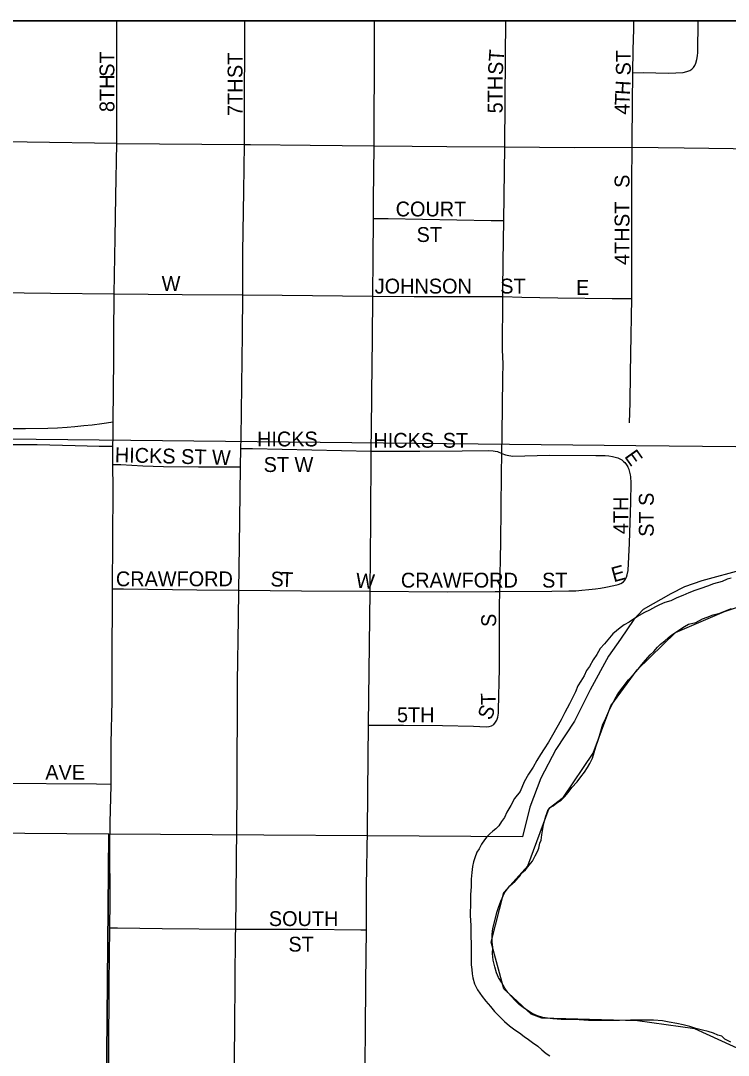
# Model space of a CAD drawing. Extents: x -17 to 88, y -5 to 22.
# Drawn here: x 3.658 to 4.109, y 20.24 to 20.9 of the extents above; entities that cross this region are included whole.
import ezdxf

# ---------------------------------------------------------------- set-up
doc = ezdxf.new("R2010")
doc.units = 0
for name, color, linetype in [('GM_X_City_Street', 7, 'Continuous'), ('GM_X_City_Street_Text', 7, 'Continuous'), ('GM_X_Corporation', 7, 'Continuous'), ('GM_X_Major_River', 7, 'Continuous'), ('GM_X_Rail_Line', 7, 'Continuous'), ('GM_X_Section', 7, 'Continuous'), ('GM_X_State_Route', 7, 'Continuous'), ('GM_X_Township', 7, 'Continuous'), ('SH_Data', 7, 'Continuous')]:
    doc.layers.add(name, color=color, linetype=linetype)

msp = doc.modelspace()

# ---------------------------------------------------------------- linework, layer by layer
at = {"layer": 'GM_X_City_Street'}
for points in [[(3.71903, 20.82161), (3.71905, 20.87247), (3.71906, 20.9)], [(3.8005, 20.82106), (3.80056, 20.85191), (3.80063, 20.88234), (3.80074, 20.9)], [(3.96636, 20.81956), (3.96675, 20.87713), (3.96712, 20.9)], [(4.04809, 20.86685), (4.04824, 20.88132), (4.04856, 20.89464), (4.04871, 20.9)], [(4.04809, 20.86685), (4.05469, 20.86693), (4.07085, 20.86659), (4.08019, 20.86695), (4.0824, 20.8675), (4.08431, 20.86828), (4.08553, 20.8691), (4.08673, 20.87018), (4.08747, 20.87139), (4.08819, 20.8729), (4.08885, 20.8752), (4.08927, 20.87749), (4.08946, 20.87962), (4.08967, 20.9)], [(4.04763, 20.81925), (4.0476, 20.82211), (4.04787, 20.84741), (4.04809, 20.86685)], [(3.79937, 20.72521), (3.79949, 20.75244), (3.80006, 20.79126), (3.8005, 20.82106)], [(3.88311, 20.8202), (3.9073, 20.81991), (3.92938, 20.81978), (3.96636, 20.81956)], [(3.96569, 20.77249), (3.96636, 20.81956)], [(3.96636, 20.81956), (4.01051, 20.81915), (4.04763, 20.81925)], [(4.04732, 20.72289), (4.04743, 20.73021), (4.04732, 20.77351), (4.04748, 20.79726), (4.04763, 20.81925)], [(4.04763, 20.81925), (4.08069, 20.81887)], [(4.08069, 20.81887), (4.12779, 20.81833)], [(3.8827, 20.77393), (3.89199, 20.77377), (3.95778, 20.77263), (3.96569, 20.77249)], [(3.96506, 20.7241), (3.96508, 20.72788), (3.96532, 20.74651), (3.96569, 20.77249)], [(3.62637, 20.72681), (3.67687, 20.72619), (3.71749, 20.72582)], [(3.71749, 20.72582), (3.76073, 20.72543), (3.79937, 20.72521)], [(3.79816, 20.6273), (3.79826, 20.63406), (3.79926, 20.70024), (3.79937, 20.72521)], [(3.79937, 20.72521), (3.82445, 20.72506), (3.88224, 20.72429)], [(3.88224, 20.72429), (3.90857, 20.7241), (3.93743, 20.7241), (3.95898, 20.7241), (3.96506, 20.7241)], [(3.96458, 20.6241), (3.96474, 20.63637), (3.96522, 20.67226), (3.96534, 20.68114), (3.96497, 20.69014), (3.96506, 20.7241)], [(3.96506, 20.7241), (3.97723, 20.7237), (4.00017, 20.72329), (4.03487, 20.72296), (4.04581, 20.72289), (4.04732, 20.72289)], [(4.04594, 20.64348), (4.04622, 20.65649), (4.04652, 20.67509), (4.04678, 20.68756), (4.04732, 20.72289)], [(3.62542, 20.6402), (3.6409, 20.64002), (3.66078, 20.63987), (3.67505, 20.64021), (3.68133, 20.64041), (3.68742, 20.64081), (3.6923, 20.64116), (3.69797, 20.6418), (3.70327, 20.64231), (3.70958, 20.64307), (3.71672, 20.64412)], [(3.62134, 20.62971), (3.6434, 20.62981), (3.65022, 20.62978), (3.66829, 20.62974), (3.69256, 20.62913), (3.70785, 20.62879), (3.7166, 20.62863)], [(3.79798, 20.61548), (3.79816, 20.6273)], [(3.79816, 20.6273), (3.80563, 20.62714), (3.88127, 20.62552)], [(3.88127, 20.62552), (3.9123, 20.62561), (3.93912, 20.62579), (3.95578, 20.6259), (3.95891, 20.62578), (3.96027, 20.62553), (3.96167, 20.6252), (3.96458, 20.6241)], [(3.96323, 20.53602), (3.96377, 20.56742), (3.96437, 20.61084), (3.96458, 20.6241)], [(3.96458, 20.6241), (3.9668, 20.62323), (3.96791, 20.6229), (3.96907, 20.62265), (3.97145, 20.62241), (3.99464, 20.62303), (4.0245, 20.62285), (4.02746, 20.62275), (4.03037, 20.62264), (4.03276, 20.62243), (4.03502, 20.62209), (4.03683, 20.62169), (4.03835, 20.62124), (4.03967, 20.62058), (4.0409, 20.61988), (4.04213, 20.61898), (4.04287, 20.61824), (4.04398, 20.61688), (4.04489, 20.61548)], [(3.71661, 20.61711), (3.72166, 20.61694), (3.73565, 20.61617), (3.74882, 20.61565), (3.77123, 20.61546), (3.79386, 20.61548), (3.79798, 20.61548)], [(3.79687, 20.53693), (3.79727, 20.56515), (3.79798, 20.61548)], [(4.04203, 20.54216), (4.04322, 20.5435), (4.04407, 20.54518), (4.04447, 20.54665), (4.04495, 20.54945), (4.0458, 20.56683), (4.04674, 20.59297), (4.04687, 20.6054), (4.04665, 20.60914), (4.04649, 20.61047), (4.04611, 20.61218), (4.04564, 20.61385), (4.04489, 20.61548)], [(3.7164, 20.53771), (3.72341, 20.53762), (3.77015, 20.53718), (3.79687, 20.53693)], [(3.96323, 20.53602), (3.99638, 20.53617), (4.00724, 20.5364), (4.01164, 20.53652), (4.01558, 20.53678), (4.01989, 20.53724), (4.02431, 20.53779), (4.02744, 20.53823), (4.03078, 20.53875), (4.03591, 20.53976), (4.03858, 20.54053), (4.04043, 20.5412), (4.04203, 20.54216)], [(3.79486, 20.32081), (3.7953, 20.36379), (3.79574, 20.40768), (3.79606, 20.47847), (3.79661, 20.51882), (3.79687, 20.53693)], [(3.79687, 20.53693), (3.83688, 20.53653), (3.88058, 20.53627)], [(3.87955, 20.45087), (3.88368, 20.45085), (3.9018, 20.45075), (3.92661, 20.4506), (3.94642, 20.45021), (3.95448, 20.4498), (3.95646, 20.44996), (3.95794, 20.45029), (3.95934, 20.4512), (3.96057, 20.4526), (3.96132, 20.45408), (3.96196, 20.45597), (3.96229, 20.45852), (3.96245, 20.46048), (3.96293, 20.48688), (3.96306, 20.52666), (3.96323, 20.53602)], [(3.88058, 20.53627), (3.92963, 20.53589), (3.96032, 20.53601), (3.96323, 20.53602)], [(3.52389, 20.41445), (3.56376, 20.41436), (3.64204, 20.41384), (3.70612, 20.4133), (3.71541, 20.41323)], [(3.71464, 20.32153), (3.71951, 20.32147), (3.74808, 20.32112), (3.79486, 20.32081)], [(3.79373, 20.17177), (3.79399, 20.21926), (3.79429, 20.25885), (3.79482, 20.31659), (3.79486, 20.32081)], [(3.79486, 20.32081), (3.80776, 20.32072), (3.8409, 20.32067), (3.87467, 20.32037), (3.87815, 20.32034)]]:
    msp.add_lwpolyline(points, dxfattribs=at)
at = {"layer": 'GM_X_Corporation'}
msp.add_line((5.58768, 20.9), (3.20786, 20.9), dxfattribs=at)
msp.add_lwpolyline([(4.11966, 20.24242), (4.08749, 20.25708), (4.05108, 20.26229), (3.98996, 20.26389), (3.98314, 20.2666), (3.9658, 20.28267), (3.95766, 20.31233), (3.96586, 20.34414), (3.98117, 20.3611), (3.99473, 20.3978), (4.00389, 20.40494), (4.0227, 20.43287), (4.03393, 20.46314), (4.05081, 20.48616), (4.07528, 20.50988), (4.10651, 20.5233), (4.1518, 20.53813)], dxfattribs=at)
at = {"layer": 'GM_X_Major_River'}
for points in [[(4.11074, 20.54453), (4.10808, 20.54379), (4.10503, 20.5423), (4.09933, 20.54082), (4.09552, 20.53933), (4.09133, 20.53785), (4.08753, 20.53674), (4.08372, 20.53525), (4.07991, 20.53338), (4.0761, 20.53189), (4.07229, 20.53002), (4.06849, 20.52892), (4.06506, 20.52742), (4.06239, 20.52631), (4.05858, 20.52406), (4.05553, 20.52256), (4.0521, 20.52069), (4.04905, 20.51882), (4.04561, 20.51657), (4.04256, 20.51469), (4.03989, 20.51282), (4.0376, 20.51094), (4.03531, 20.50906), (4.02994, 20.50265), (4.02726, 20.49963), (4.02496, 20.49586), (4.02266, 20.49246), (4.02035, 20.4883), (4.01843, 20.48566), (4.01689, 20.48226), (4.01496, 20.47886), (4.01304, 20.47584), (4.0115, 20.47206), (4.00957, 20.46827), (4.00764, 20.46449), (4.00457, 20.45883), (4.00225, 20.45429), (3.99956, 20.44938), (3.99687, 20.44447), (3.99418, 20.43993), (3.99149, 20.43578)], [(3.99539, 20.39819), (3.9973, 20.39931), (3.99959, 20.40119), (4.00226, 20.40307), (4.00456, 20.40533), (4.00685, 20.40796), (4.00915, 20.41098), (4.0126, 20.41475), (4.0149, 20.41777), (4.0172, 20.42079), (4.01912, 20.42381), (4.02066, 20.42645), (4.0222, 20.42985), (4.02336, 20.43326), (4.02453, 20.43705), (4.02609, 20.44197), (4.02764, 20.44689), (4.02881, 20.45143), (4.03074, 20.45521), (4.03267, 20.45975), (4.0346, 20.46353), (4.03652, 20.46731), (4.03845, 20.47071), (4.04535, 20.47977), (4.04841, 20.48316), (4.05147, 20.48655), (4.05377, 20.48956), (4.05607, 20.4922), (4.05913, 20.49559), (4.06142, 20.49785), (4.06372, 20.50049), (4.06564, 20.50238), (4.06831, 20.50463), (4.0706, 20.50651), (4.07289, 20.50839), (4.07594, 20.51027), (4.07861, 20.51214), (4.0809, 20.51364), (4.08357, 20.51514), (4.08814, 20.51624), (4.09233, 20.51849), (4.09538, 20.5196), (4.09918, 20.52109), (4.10337, 20.5222), (4.10718, 20.52369), (4.11098, 20.52518)], [(3.99149, 20.43578), (3.98918, 20.432), (3.98688, 20.42823), (3.98457, 20.42407), (3.9815, 20.41954), (3.9788, 20.41463), (3.9761, 20.40858), (3.97265, 20.40405), (3.97034, 20.39952), (3.96765, 20.39536), (3.96611, 20.39196), (3.96419, 20.38932), (3.96265, 20.38667), (3.96074, 20.38479), (3.95883, 20.38329), (3.95692, 20.38141), (3.95501, 20.37952), (3.95348, 20.37764), (3.95156, 20.375), (3.95002, 20.37197), (3.94848, 20.36971), (3.94732, 20.3663), (3.94654, 20.36365), (3.94576, 20.36062), (3.94535, 20.35683), (3.94494, 20.35266), (3.94491, 20.34773), (3.94449, 20.3428), (3.94446, 20.33787), (3.94439, 20.32952), (3.94473, 20.32307), (3.94468, 20.317), (3.94501, 20.31054), (3.94492, 20.29802), (3.94528, 20.29499), (3.94564, 20.29232), (3.946, 20.28967), (3.94711, 20.28586), (3.94898, 20.28205), (3.95199, 20.27786), (3.95425, 20.27481), (3.95726, 20.27137), (3.9599, 20.26831), (3.96291, 20.26525), (3.9663, 20.26181), (3.96932, 20.25913), (3.97272, 20.25645), (3.97574, 20.25453), (3.97876, 20.25223), (3.98141, 20.25031), (3.98405, 20.2484), (3.98745, 20.24609), (3.9901, 20.2438), (3.99274, 20.2415), (3.995, 20.23997)], [(4.11049, 20.24857), (4.10671, 20.2505), (4.10483, 20.25241), (4.10217, 20.25319), (4.09953, 20.25434), (4.09612, 20.25551), (4.09232, 20.2563), (4.08816, 20.25747), (4.08437, 20.25864), (4.0802, 20.25981), (4.07603, 20.2606), (4.0711, 20.26139), (4.06693, 20.26218), (4.06124, 20.2626), (4.0563, 20.26264), (4.05174, 20.26268), (4.04643, 20.26272), (4.03959, 20.26239), (4.03276, 20.26244), (4.0263, 20.26249), (4.01985, 20.26254), (4.01378, 20.26297), (4.0077, 20.26302), (4.00239, 20.26306), (3.99707, 20.26347), (3.99366, 20.26388), (3.99062, 20.26428), (3.98721, 20.26545), (3.98381, 20.26699), (3.98078, 20.26891), (3.97814, 20.27083), (3.97549, 20.27275), (3.97286, 20.27542), (3.9706, 20.27772), (3.96834, 20.28039), (3.96646, 20.28306), (3.96421, 20.28687), (3.96233, 20.28992), (3.96121, 20.29296), (3.9601, 20.29677), (3.95899, 20.30095), (3.95864, 20.30513), (3.95867, 20.30892), (3.95832, 20.31272), (3.95835, 20.31727), (3.95876, 20.32106), (3.9615, 20.33205), (3.96266, 20.33507), (3.96382, 20.33848), (3.96537, 20.34188), (3.96653, 20.34453), (3.96806, 20.34641), (3.96959, 20.3483), (3.97303, 20.35131), (3.97571, 20.35432), (3.97724, 20.35659), (3.97953, 20.35847), (3.98184, 20.36149), (3.98413, 20.36412), (3.98568, 20.36753), (3.98721, 20.37017), (3.98799, 20.37244), (3.98877, 20.37547), (3.98954, 20.37736), (3.98995, 20.38077), (3.99035, 20.38343), (3.99075, 20.38608), (3.99153, 20.38873), (3.99231, 20.39214), (3.99309, 20.39441), (3.99386, 20.3963), (3.99539, 20.39819)]]:
    msp.add_lwpolyline(points, dxfattribs=at)
at = {"layer": 'GM_X_Rail_Line'}
msp.add_lwpolyline([(3.33784, 20.63494), (3.42428, 20.63515), (3.66767, 20.63326), (4.04986, 20.62913), (4.41143, 20.62553), (4.69708, 20.62244), (4.78173, 20.62035), (4.83124, 20.61775), (4.87795, 20.61471), (5.02378, 20.6032), (5.35564, 20.57743), (5.53204, 20.56318), (5.63047, 20.55545), (5.71669, 20.54875), (6.32595, 20.50065), (6.53551, 20.48433), (6.65266, 20.47472), (6.95205, 20.45153), (7.27068, 20.42662), (7.45962, 20.41202), (8.17109, 20.35637), (8.73122, 20.31274), (9.05827, 20.28714), (9.4, 20.26034)], dxfattribs=at)
at = {"layer": 'GM_X_Section'}
for points in [[(2.68666, 20.9), (2.68345, 20.1757), (3.71204, 20.17028), (3.71394, 20.3813), (3.41881, 20.38356), (3.42344, 20.9)], [(4.11857, 20.55006), (4.09199, 20.54273), (4.08097, 20.53903), (4.07221, 20.53457), (4.05469, 20.52449), (4.04857, 20.51811), (4.04012, 20.50568), (4.03245, 20.49476), (4.02089, 20.47327), (4.01086, 20.45328), (3.99896, 20.43519), (3.98932, 20.4171), (3.98233, 20.39859), (3.97762, 20.37969), (3.71394, 20.3813), (3.71204, 20.17028), (3.7219, 20.17019), (4.7146, 20.17531)]]:
    msp.add_lwpolyline(points, dxfattribs=at)
at = {"layer": 'GM_X_State_Route'}
for points in [[(3.88311, 20.8202), (3.88326, 20.8859), (3.88344, 20.9)], [(3.71903, 20.82161), (3.66193, 20.82246), (3.60534, 20.82288), (3.55935, 20.82357), (3.52839, 20.82388), (3.48662, 20.82431), (3.44748, 20.82449), (3.4259, 20.82461)], [(3.71665, 20.63482), (3.71672, 20.64412), (3.71718, 20.68438), (3.71722, 20.69932), (3.71749, 20.72582), (3.71806, 20.76161), (3.71849, 20.78812), (3.71903, 20.82161)], [(3.71903, 20.82161), (3.8005, 20.82106), (3.80437, 20.82104), (3.84237, 20.8206), (3.88311, 20.8202)], [(3.88139, 20.63749), (3.88163, 20.66267), (3.88197, 20.6974), (3.88224, 20.72429), (3.88247, 20.74907), (3.8827, 20.77393), (3.8828, 20.78567), (3.88311, 20.8202)], [(3.87827, 20.34126), (3.87829, 20.34821), (3.87883, 20.38351), (3.87933, 20.43065), (3.87955, 20.45087), (3.87955, 20.45104), (3.88058, 20.53627), (3.88093, 20.58133), (3.88127, 20.62552), (3.8813, 20.62915), (3.88139, 20.63749)], [(3.71363, 20.21548), (3.71396, 20.241), (3.7142, 20.28577), (3.71464, 20.32153), (3.71484, 20.3384), (3.71465, 20.37439), (3.71492, 20.38863), (3.71541, 20.41231), (3.71541, 20.41323), (3.71548, 20.43901), (3.71606, 20.46624), (3.71622, 20.4978), (3.71627, 20.5282), (3.7164, 20.53771), (3.71657, 20.56923), (3.71675, 20.60152), (3.71661, 20.61711), (3.7166, 20.62863), (3.71665, 20.63482)], [(3.87902, 20.10973), (3.87948, 20.13681), (3.8796, 20.15415), (3.8795, 20.17145), (3.87945, 20.18219), (3.87932, 20.1885), (3.87908, 20.19275), (3.87779, 20.22658), (3.87741, 20.23657), (3.87756, 20.25519), (3.8778, 20.28698), (3.87815, 20.32034), (3.87822, 20.32775), (3.87827, 20.34126)]]:
    msp.add_lwpolyline(points, dxfattribs=at)
at = {"layer": 'GM_X_Township'}
msp.add_line((7.72185, 20.9), (2.68822, 20.9), dxfattribs=at)
at = {"layer": 'SH_Data'}
msp.add_line((2.6, 20.9), (9.4, 20.9), dxfattribs=at)

# ---------------------------------------------------------------- texts
at = {"layer": 'GM_X_City_Street_Text'}
for s, rotation, p in [('ST', 86.42535, (3.96505, 20.86519)), ('ST', 90, (4.04671, 20.86508)), ('ST', 90, (3.71754, 20.86424)), ('ST', 90, (3.79921, 20.86341)), ('8TH', 90, (3.71754, 20.84174)), ('7TH', 90, (3.79921, 20.83924)), ('5TH', 90, (3.96504, 20.84091)), ('H', 86.69771, (4.04617, 20.85243)), ('T', 87.97798, (4.04593, 20.84582)), ('4', 89.40676, (4.04587, 20.84005)), ('S', 90, (4.04587, 20.79341)), ('COURT', 0.00001, (3.89682, 20.77519)), ('ST', 90, (4.04587, 20.76841)), ('ST', 0.00001, (3.91016, 20.7589)), ('4TH', 90, (4.04587, 20.74424)), ('W', 0.00001, (3.74766, 20.72769)), ('JOHNSON', 0.00001, (3.88349, 20.72603)), ('ST', 0.00001, (3.96349, 20.72603)), ('E', 0.00001, (4.01182, 20.72519)), ('HICKS', 0.00001, (3.80849, 20.62853)), ('HICKS', 0.00001, (3.88266, 20.62769)), ('ST', 0.00001, (3.92682, 20.62769)), ('HICKS ST W', 358.53177, (3.71773, 20.61852)), ('E', 305.2252, (4.04229, 20.62214)), ('ST W', 0.00001, (3.81266, 20.61223)), ('ST S', 90, (4.06133, 20.57091)), ('4TH', 90, (4.04504, 20.57257)), ('E', 15.2454, (4.03581, 20.54186)), ('CRAWFORD', 0.00001, (3.71849, 20.53936)), ('S', 357.64932, (3.8169, 20.53936)), ('T', 357.64296, (3.82356, 20.53908)), ('W', 355.23937, (3.87114, 20.53852)), ('CRAWFORD', 0.00001, (3.90016, 20.53852)), ('ST', 0.00001, (3.99016, 20.53852)), ('S', 90, (3.96087, 20.51341)), ('T', 90.94973, (3.9607, 20.46364)), ('5TH', 0.00001, (3.89766, 20.45269)), ('S', 68.16814, (3.95748, 20.45343)), ('AVE', 0.00001, (3.67349, 20.41602)), ('SOUTH', 0.00001, (3.81599, 20.3227)), ('ST', 0.00001, (3.82849, 20.3064))]:
    msp.add_text(s, height=0.00947, rotation=rotation, dxfattribs=at).set_placement(p)

doc.saveas('drawing.dxf')
